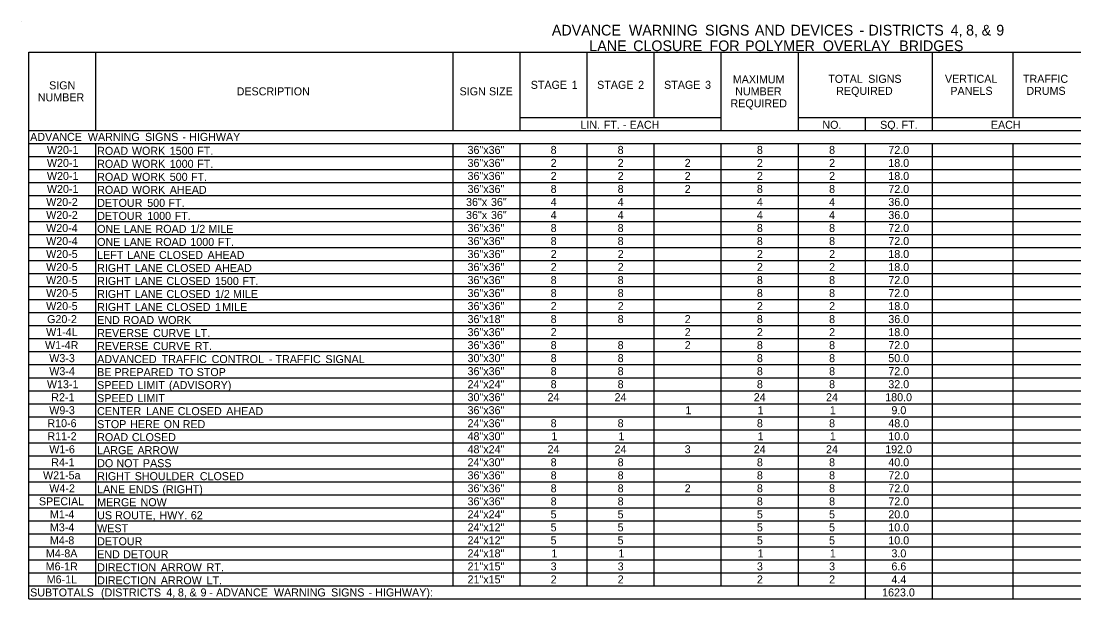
# Model space of a CAD drawing. Extents: x 544420 to 1930787, y -1947044 to 596640.
# Drawn here: x 544420 to 545209, y -1946626 to -1946193 of the extents above; entities that cross this region are included whole.
import ezdxf

# ---------------------------------------------------------------- set-up
doc = ezdxf.new("R2010")
doc.units = 0
doc.layers.add('Default', color=7, linetype='Continuous')

msp = doc.modelspace()

# ---------------------------------------------------------------- linework, layer by layer
at = {"layer": 'Default'}
for p, q in [((544420.05, -1946193.36), (544420.05, -1946193.36)), ((544425.9, -1946216.76), (545626.13, -1946216.76)), ((544425.9, -1946626.26), (544425.9, -1946216.76)), ((544425.9, -1946626.26), (544425.9, -1946216.76)), ((544476.12, -1946275.26), (544476.12, -1946216.76)), ((544743.75, -1946275.26), (544743.75, -1946216.76)), ((544793.97, -1946275.26), (544793.97, -1946216.76)), ((544844.18, -1946265.51), (544844.18, -1946216.76)), ((544894.39, -1946265.51), (544894.39, -1946216.76)), ((544944.6, -1946275.26), (544944.6, -1946216.76)), ((545002.62, -1946275.26), (545002.62, -1946216.76)), ((545103.04, -1946275.26), (545103.04, -1946216.76)), ((545163.49, -1946265.51), (545163.49, -1946216.76)), ((544793.97, -1946265.51), (544944.6, -1946265.51)), ((544944.6, -1946275.26), (544944.6, -1946265.51)), ((545002.62, -1946265.51), (545626.13, -1946265.51)), ((545052.83, -1946275.26), (545052.83, -1946265.51)), ((544425.9, -1946275.26), (545626.13, -1946275.26)), ((544944.6, -1946275.26), (545626.13, -1946275.26)), ((544425.9, -1946285.01), (545626.13, -1946285.01)), ((544476.12, -1946558.01), (544476.12, -1946285.01)), ((544476.12, -1946616.51), (544476.12, -1946285.01)), ((544743.75, -1946558.01), (544743.75, -1946285.01)), ((544743.75, -1946616.51), (544743.75, -1946285.01)), ((544793.97, -1946558.01), (544793.97, -1946285.01)), ((544793.97, -1946616.51), (544793.97, -1946285.01)), ((544844.18, -1946558.01), (544844.18, -1946285.01)), ((544844.18, -1946616.51), (544844.18, -1946285.01)), ((544894.39, -1946558.01), (544894.39, -1946285.01)), ((544894.39, -1946616.51), (544894.39, -1946285.01)), ((544944.6, -1946558.01), (544944.6, -1946285.01)), ((544944.6, -1946616.51), (544944.6, -1946285.01)), ((545002.62, -1946616.51), (545002.62, -1946285.01)), ((545052.83, -1946616.51), (545052.83, -1946285.01)), ((545052.83, -1946626.26), (545052.83, -1946285.01)), ((545103.04, -1946548.26), (545103.04, -1946285.01)), ((545103.04, -1946626.26), (545103.04, -1946285.01)), ((545163.49, -1946558.01), (545163.49, -1946285.01)), ((545163.49, -1946626.26), (545163.49, -1946285.01)), ((544425.9, -1946294.76), (545626.13, -1946294.76)), ((544425.9, -1946304.51), (545626.13, -1946304.51)), ((544425.9, -1946314.26), (545626.13, -1946314.26)), ((544425.9, -1946324.01), (545626.13, -1946324.01)), ((544425.9, -1946333.76), (545626.13, -1946333.76)), ((544425.9, -1946343.51), (545626.13, -1946343.51)), ((544425.9, -1946353.26), (545626.13, -1946353.26)), ((544425.9, -1946363.01), (545626.13, -1946363.01)), ((544425.9, -1946372.76), (545626.13, -1946372.76)), ((544425.9, -1946382.51), (545626.13, -1946382.51)), ((544425.9, -1946392.26), (545626.13, -1946392.26)), ((544425.9, -1946402.01), (545626.13, -1946402.01)), ((544425.9, -1946411.76), (545626.13, -1946411.76)), ((544425.9, -1946421.51), (545626.13, -1946421.51)), ((544425.9, -1946431.26), (545626.13, -1946431.26)), ((544425.9, -1946441.01), (545626.13, -1946441.01)), ((544425.9, -1946450.76), (545626.13, -1946450.76)), ((544425.9, -1946460.51), (545626.13, -1946460.51)), ((544425.9, -1946470.26), (545626.13, -1946470.26)), ((544425.9, -1946480.01), (545626.13, -1946480.01)), ((544425.9, -1946489.76), (545626.13, -1946489.76)), ((544425.9, -1946499.51), (545626.13, -1946499.51)), ((544425.9, -1946509.26), (545626.13, -1946509.26)), ((544425.9, -1946519.01), (545626.13, -1946519.01)), ((544425.9, -1946528.76), (545626.13, -1946528.76)), ((544425.9, -1946538.51), (545626.13, -1946538.51)), ((544425.9, -1946548.26), (545626.13, -1946548.26)), ((544425.9, -1946558.01), (545626.13, -1946558.01)), ((544425.9, -1946567.76), (545626.13, -1946567.76)), ((544425.9, -1946577.51), (545626.13, -1946577.51)), ((544425.9, -1946587.26), (545626.13, -1946587.26)), ((544425.9, -1946597.01), (545626.13, -1946597.01)), ((544425.9, -1946606.76), (545626.13, -1946606.76)), ((544425.9, -1946616.51), (545626.13, -1946616.51)), ((544944.6, -1946616.51), (545103.04, -1946616.51)), ((545103.04, -1946616.51), (545626.13, -1946616.51)), ((545103.04, -1946626.26), (545103.04, -1946616.51)), ((545163.49, -1946626.26), (545163.49, -1946616.51)), ((544425.9, -1946626.26), (545626.13, -1946626.26))]:
    msp.add_line(p, q, dxfattribs=at)

# ---------------------------------------------------------------- texts
for s, height, p in [('ADVANCE', 8, (544817.83, -1946204.18)), (' WARNING', 8, (544872.56, -1946204.18)), (' SIGNS', 8, (544929.62, -1946204.18)), (' AND', 8, (544966.96, -1946204.18)), (' DEVICES', 8, (544993.73, -1946204.18)), (' DISTRICTS', 8, (545052.11, -1946204.18)), (' 4,', 8, (545113.67, -1946204.18)), (' 8,', 8, (545125.28, -1946204.18)), (' &', 8, (545136.9, -1946204.18)), (' 9', 8, (545147.89, -1946204.18)), (' -', 8, (545045.37, -1946204.18)), ('LANE', 8, (544845.9, -1946215.88)), (' CLOSURE', 8, (544875.78, -1946215.88)), (' FOR', 8, (544932.99, -1946215.88)), (' POLYMER', 8, (544959.64, -1946215.88)), (' OVERLAY', 8, (545017.96, -1946215.88)), (' BRIDGES', 8, (545075.13, -1946215.88)), ('MAXIMUM', 6, (544953.42, -1946240.01)), ('TOTAL', 6, (545024.98, -1946239.63)), (' SIGNS', 6, (545052.67, -1946239.63)), ('VERTICAL', 6, (545112.43, -1946239.63)), ('TRAFFIC', 6, (545170.88, -1946239.63)), ('SIGN', 6, (544441.1, -1946244.51)), ('DESCRIPTION', 6, (544581.62, -1946249.01)), ('SIGN', 6, (544748.67, -1946249.01)), (' SIZE', 6, (544768.5, -1946249.01)), ('STAGE', 6, (544802.02, -1946244.13)), (' 1', 6, (544830.49, -1946244.13)), ('STAGE', 6, (544851.77, -1946244.13)), (' 2', 6, (544880.24, -1946244.13)), ('STAGE', 6, (544901.95, -1946244.13)), (' 3', 6, (544930.42, -1946244.13)), ('NUMBER', 6, (544955.23, -1946249.01)), ('REQUIRED', 6, (545030.91, -1946248.63)), ('PANELS', 6, (545116.47, -1946248.63)), ('DRUMS', 6, (545173.43, -1946248.63)), ('NUMBER', 6, (544432.63, -1946253.51)), ('REQUIRED', 6, (544951.69, -1946258.01)), ('LIN.', 6, (544839.25, -1946274.06)), (' FT.', 6, (544854.5, -1946274.06)), (' -', 6, (544868.83, -1946274.06)), (' EACH', 6, (544873.88, -1946274.06)), ('NO.', 6, (545020.56, -1946274.06)), ('SQ.', 6, (545063.84, -1946274.06)), (' FT.', 6, (545077.71, -1946274.06)), ('EACH', 6, (545146.82, -1946274.06)), ('ADVANCE', 6, (544426.88, -1946283.13)), (' WARNING', 6, (544467.92, -1946283.13)), (' SIGNS', 6, (544510.72, -1946283.13)), (' -', 6, (544538.73, -1946283.13)), (' HIGHWAY', 6, (544543.79, -1946283.13)), ('W20-1', 6, (544439.44, -1946292.88)), ('ROAD', 6, (544477.09, -1946293.56)), (' WORK', 6, (544500.87, -1946293.56)), (' 1500', 6, (544529.26, -1946293.56)), (' FT.', 6, (544549.82, -1946293.56)), ('36"x36"', 6, (544754.66, -1946292.88)), ('8', 6, (544816.93, -1946292.88)), ('8', 6, (544867.14, -1946292.88)), ('8', 6, (544971.47, -1946292.88)), ('8', 6, (545025.58, -1946292.88)), ('72.0', 6, (545069.98, -1946292.88)), ('W20-1', 6, (544439.44, -1946302.63)), ('ROAD', 6, (544477.09, -1946303.31)), (' WORK', 6, (544500.87, -1946303.31)), (' 1000', 6, (544529.26, -1946303.31)), (' FT.', 6, (544549.82, -1946303.31)), ('36"x36"', 6, (544754.66, -1946302.63)), ('2', 6, (544816.96, -1946302.63)), ('2', 6, (544867.18, -1946302.63)), ('2', 6, (544917.39, -1946302.63)), ('2', 6, (544971.5, -1946302.63)), ('2', 6, (545025.61, -1946302.63)), ('18.0', 6, (545069.98, -1946302.63)), ('W20-1', 6, (544439.44, -1946312.38)), ('36"x36"', 6, (544754.66, -1946312.38)), ('2', 6, (544816.96, -1946312.38)), ('2', 6, (544867.18, -1946312.38)), ('2', 6, (544917.39, -1946312.38)), ('2', 6, (544971.5, -1946312.38)), ('2', 6, (545025.61, -1946312.38)), ('18.0', 6, (545069.98, -1946312.38)), ('ROAD', 6, (544477.09, -1946313.06)), (' WORK', 6, (544500.87, -1946313.06)), (' 500', 6, (544529.26, -1946313.06)), (' FT.', 6, (544545.16, -1946313.06)), ('W20-1', 6, (544439.44, -1946322.13)), ('ROAD', 6, (544477.09, -1946322.81)), (' WORK', 6, (544500.87, -1946322.81)), (' AHEAD', 6, (544529.26, -1946322.81)), ('36"x36"', 6, (544754.66, -1946322.13)), ('8', 6, (544816.93, -1946322.13)), ('8', 6, (544867.14, -1946322.13)), ('2', 6, (544917.39, -1946322.13)), ('8', 6, (544971.47, -1946322.13)), ('8', 6, (545025.58, -1946322.13)), ('72.0', 6, (545069.98, -1946322.13)), ('W20-2', 6, (544438.89, -1946331.88)), ('DETOUR', 6, (544477.09, -1946332.56)), (' 500', 6, (544512.38, -1946332.56)), (' FT.', 6, (544528.28, -1946332.56)), ('36"x', 6, (544753.53, -1946331.88)), (' 36"', 6, (544769.96, -1946331.88)), ('4', 6, (544816.95, -1946331.88)), ('4', 6, (544867.16, -1946331.88)), ('4', 6, (544971.48, -1946331.88)), ('4', 6, (545025.6, -1946331.88)), ('36.0', 6, (545069.98, -1946331.88)), ('W20-2', 6, (544438.89, -1946341.63)), ('DETOUR', 6, (544477.09, -1946342.31)), (' 1000', 6, (544512.38, -1946342.31)), (' FT.', 6, (544532.94, -1946342.31)), ('36"x', 6, (544753.53, -1946341.63)), (' 36"', 6, (544769.96, -1946341.63)), ('4', 6, (544816.95, -1946341.63)), ('4', 6, (544867.16, -1946341.63)), ('4', 6, (544971.48, -1946341.63)), ('4', 6, (545025.6, -1946341.63)), ('36.0', 6, (545069.98, -1946341.63)), ('W20-4', 6, (544438.87, -1946351.38)), ('ONE', 6, (544477.09, -1946352.06)), (' LANE', 6, (544494.81, -1946352.06)), (' ROAD', 6, (544518.59, -1946352.06)), (' 1/2', 6, (544544.7, -1946352.06)), (' MILE', 6, (544558.23, -1946352.06)), ('36"x36"', 6, (544754.66, -1946351.38)), ('8', 6, (544816.93, -1946351.38)), ('8', 6, (544867.14, -1946351.38)), ('8', 6, (544971.47, -1946351.38)), ('8', 6, (545025.58, -1946351.38)), ('72.0', 6, (545069.98, -1946351.38)), ('W20-4', 6, (544438.87, -1946361.13)), ('ONE', 6, (544477.09, -1946361.81)), (' LANE', 6, (544494.81, -1946361.81)), (' ROAD', 6, (544518.59, -1946361.81)), (' 1000', 6, (544544.7, -1946361.81)), (' FT.', 6, (544565.26, -1946361.81)), ('36"x36"', 6, (544754.66, -1946361.13)), ('8', 6, (544816.93, -1946361.13)), ('8', 6, (544867.14, -1946361.13)), ('8', 6, (544971.47, -1946361.13)), ('8', 6, (545025.58, -1946361.13)), ('72.0', 6, (545069.98, -1946361.13)), ('W20-5', 6, (544438.84, -1946370.88)), ('LEFT', 6, (544477.09, -1946371.56)), (' LANE', 6, (544497.42, -1946371.56)), (' CLOSED', 6, (544521.2, -1946371.56)), (' AHEAD', 6, (544557.56, -1946371.56)), ('36"x36"', 6, (544754.66, -1946370.88)), ('2', 6, (544816.96, -1946370.88)), ('2', 6, (544867.18, -1946370.88)), ('2', 6, (544971.5, -1946370.88)), ('2', 6, (545025.61, -1946370.88)), ('18.0', 6, (545069.98, -1946370.88)), ('W20-5', 6, (544438.84, -1946380.63)), ('RIGHT', 6, (544477.09, -1946381.31)), (' LANE', 6, (544503, -1946381.31)), (' CLOSED', 6, (544526.78, -1946381.31)), (' AHEAD', 6, (544563.14, -1946381.31)), ('36"x36"', 6, (544754.66, -1946380.63)), ('2', 6, (544816.96, -1946380.63)), ('2', 6, (544867.18, -1946380.63)), ('2', 6, (544971.5, -1946380.63)), ('2', 6, (545025.61, -1946380.63)), ('18.0', 6, (545069.98, -1946380.63)), ('W20-5', 6, (544438.84, -1946390.38)), ('RIGHT', 6, (544477.09, -1946391.06)), (' LANE', 6, (544503, -1946391.06)), (' CLOSED', 6, (544526.78, -1946391.06)), (' 1500', 6, (544563.14, -1946391.06)), (' FT.', 6, (544583.71, -1946391.06)), ('36"x36"', 6, (544754.66, -1946390.38)), ('8', 6, (544816.93, -1946390.38)), ('8', 6, (544867.14, -1946390.38)), ('8', 6, (544971.47, -1946390.38)), ('8', 6, (545025.58, -1946390.38)), ('72.0', 6, (545069.98, -1946390.38)), ('W20-5', 6, (544438.84, -1946400.13)), ('RIGHT', 6, (544477.09, -1946400.81)), (' LANE', 6, (544503, -1946400.81)), (' CLOSED', 6, (544526.78, -1946400.81)), (' 1/2', 6, (544563.14, -1946400.81)), (' MILE', 6, (544576.67, -1946400.81)), ('36"x36"', 6, (544754.66, -1946400.13)), ('8', 6, (544816.93, -1946400.13)), ('8', 6, (544867.14, -1946400.13)), ('8', 6, (544971.47, -1946400.13)), ('8', 6, (545025.58, -1946400.13)), ('72.0', 6, (545069.98, -1946400.13)), ('W20-5', 6, (544438.84, -1946409.88)), ('RIGHT', 6, (544477.09, -1946410.56)), (' LANE', 6, (544503, -1946410.56)), (' CLOSED', 6, (544526.78, -1946410.56)), (' 1', 6, (544563.14, -1946410.56)), (' MILE', 6, (544568.59, -1946410.56)), ('36"x36"', 6, (544754.66, -1946409.88)), ('2', 6, (544816.96, -1946409.88)), ('2', 6, (544867.18, -1946409.88)), ('2', 6, (544971.5, -1946409.88)), ('2', 6, (545025.61, -1946409.88)), ('18.0', 6, (545069.98, -1946409.88)), ('G20-2', 6, (544439.59, -1946419.63)), ('END', 6, (544477.09, -1946420.31)), (' ROAD', 6, (544494.35, -1946420.31)), (' WORK', 6, (544520.45, -1946420.31)), ('36"x18"', 6, (544754.66, -1946419.63)), ('8', 6, (544816.93, -1946419.63)), ('8', 6, (544867.14, -1946419.63)), ('2', 6, (544917.39, -1946419.63)), ('8', 6, (544971.47, -1946419.63)), ('8', 6, (545025.58, -1946419.63)), ('36.0', 6, (545069.98, -1946419.63)), ('W1-4L', 6, (544438.82, -1946429.38)), ('REVERSE', 6, (544477.09, -1946430.06)), (' CURVE', 6, (544516.72, -1946430.06)), (' LT.', 6, (544547.95, -1946430.06)), ('36"x36"', 6, (544754.66, -1946429.38)), ('2', 6, (544816.96, -1946429.38)), ('2', 6, (544917.39, -1946429.38)), ('2', 6, (544971.5, -1946429.38)), ('2', 6, (545025.61, -1946429.38)), ('18.0', 6, (545069.98, -1946429.38)), ('W1-4R', 6, (544438.03, -1946439.13)), ('36"x36"', 6, (544754.66, -1946439.13)), ('8', 6, (544816.93, -1946439.13)), ('8', 6, (544867.14, -1946439.13)), ('2', 6, (544917.39, -1946439.13)), ('8', 6, (544971.47, -1946439.13)), ('8', 6, (545025.58, -1946439.13)), ('72.0', 6, (545069.98, -1946439.13)), ('REVERSE', 6, (544477.09, -1946439.81)), (' CURVE', 6, (544516.72, -1946439.81)), (' RT.', 6, (544547.95, -1946439.81)), ('W3-3', 6, (544441.19, -1946448.88)), ('ADVANCED', 6, (544477.09, -1946449.56)), (' TRAFFIC', 6, (544523.23, -1946449.56)), (' CONTROL', 6, (544560.63, -1946449.56)), (' -', 6, (544603.64, -1946449.56)), (' TRAFFIC', 6, (544608.5, -1946449.56)), (' SIGNAL', 6, (544645.89, -1946449.56)), ('30"x30"', 6, (544754.66, -1946448.88)), ('8', 6, (544816.93, -1946448.88)), ('8', 6, (544867.14, -1946448.88)), ('8', 6, (544971.47, -1946448.88)), ('8', 6, (545025.58, -1946448.88)), ('50.0', 6, (545069.98, -1946448.88)), ('W3-4', 6, (544441.2, -1946458.63)), ('BE', 6, (544477.09, -1946459.31)), (' PREPARED', 6, (544487.83, -1946459.31)), (' TO', 6, (544535.84, -1946459.31)), (' STOP', 6, (544549.43, -1946459.31)), ('36"x36"', 6, (544754.66, -1946458.63)), ('8', 6, (544816.93, -1946458.63)), ('8', 6, (544867.14, -1946458.63)), ('8', 6, (544971.47, -1946458.63)), ('8', 6, (545025.58, -1946458.63)), ('72.0', 6, (545069.98, -1946458.63)), ('W13-1', 6, (544439.44, -1946468.38)), ('SPEED', 6, (544477.09, -1946469.06)), (' LIMIT', 6, (544505.07, -1946469.06)), (' (ADVISORY)', 6, (544528.65, -1946469.06)), ('24"x24"', 6, (544754.66, -1946468.38)), ('8', 6, (544816.93, -1946468.38)), ('8', 6, (544867.14, -1946468.38)), ('8', 6, (544971.47, -1946468.38)), ('8', 6, (545025.58, -1946468.38)), ('32.0', 6, (545069.98, -1946468.38)), ('R2-1', 6, (544442.7, -1946478.13)), ('30"x36"', 6, (544754.66, -1946478.13)), ('24', 6, (544814.62, -1946478.13)), ('24', 6, (544864.83, -1946478.13)), ('24', 6, (544969.15, -1946478.13)), ('24', 6, (545023.27, -1946478.13)), ('180.0', 6, (545067.65, -1946478.13)), ('SPEED', 6, (544477.09, -1946478.81)), (' LIMIT', 6, (544505.07, -1946478.81)), ('W9-3', 6, (544441.19, -1946487.88)), ('CENTER', 6, (544477.09, -1946488.56)), (' LANE', 6, (544511.45, -1946488.56)), (' CLOSED', 6, (544535.23, -1946488.56)), (' AHEAD', 6, (544571.59, -1946488.56)), ('36"x36"', 6, (544754.66, -1946487.88)), ('1', 6, (544917.94, -1946487.88)), ('1', 6, (544972.05, -1946487.88)), ('1', 6, (545026.16, -1946487.88)), ('9.0', 6, (545072.31, -1946487.88)), ('R10-6', 6, (544439.79, -1946497.63)), ('STOP', 6, (544477.09, -1946498.31)), (' HERE', 6, (544499.55, -1946498.31)), (' ON', 6, (544524.73, -1946498.31)), (' RED', 6, (544538.95, -1946498.31)), ('24"x36"', 6, (544754.66, -1946497.63)), ('8', 6, (544816.93, -1946497.63)), ('8', 6, (544867.14, -1946497.63)), ('8', 6, (544971.47, -1946497.63)), ('8', 6, (545025.58, -1946497.63)), ('48.0', 6, (545069.98, -1946497.63)), ('R11-2', 6, (544439.82, -1946507.38)), ('ROAD', 6, (544477.09, -1946508.06)), (' CLOSED', 6, (544500.87, -1946508.06)), ('48"x30"', 6, (544754.66, -1946507.38)), ('1', 6, (544817.51, -1946507.38)), ('1', 6, (544867.73, -1946507.38)), ('1', 6, (544972.05, -1946507.38)), ('1', 6, (545026.16, -1946507.38)), ('10.0', 6, (545069.98, -1946507.38)), ('W1-6', 6, (544441.19, -1946517.13)), ('LARGE', 6, (544477.09, -1946517.81)), (' ARROW', 6, (544505.07, -1946517.81)), ('48"x24"', 6, (544754.66, -1946517.13)), ('24', 6, (544814.62, -1946517.13)), ('24', 6, (544864.83, -1946517.13)), ('3', 6, (544917.36, -1946517.13)), ('24', 6, (544969.15, -1946517.13)), ('24', 6, (545023.27, -1946517.13)), ('192.0', 6, (545067.65, -1946517.13)), ('R4-1', 6, (544442.7, -1946526.88)), ('DO', 6, (544477.09, -1946527.56)), (' NOT', 6, (544489.29, -1946527.56)), (' PASS', 6, (544509.15, -1946527.56)), ('24"x30"', 6, (544754.66, -1946526.88)), ('8', 6, (544816.93, -1946526.88)), ('8', 6, (544867.14, -1946526.88)), ('8', 6, (544971.47, -1946526.88)), ('8', 6, (545025.58, -1946526.88)), ('40.0', 6, (545069.98, -1946526.88)), ('W21-5a', 6, (544436.52, -1946536.63)), ('RIGHT', 6, (544477.09, -1946537.31)), (' SHOULDER', 6, (544503, -1946537.31)), (' CLOSED', 6, (544551.8, -1946537.31)), ('36"x36"', 6, (544754.66, -1946536.63)), ('8', 6, (544816.93, -1946536.63)), ('8', 6, (544867.14, -1946536.63)), ('8', 6, (544971.47, -1946536.63)), ('8', 6, (545025.58, -1946536.63)), ('72.0', 6, (545069.98, -1946536.63)), ('W4-2', 6, (544441.22, -1946546.38)), ('LANE', 6, (544477.09, -1946547.06)), (' ENDS', 6, (544498.54, -1946547.06)), (' (RIGHT)', 6, (544523.73, -1946547.06)), ('36"x36"', 6, (544754.66, -1946546.38)), ('8', 6, (544816.93, -1946546.38)), ('8', 6, (544867.14, -1946546.38)), ('2', 6, (544917.39, -1946546.38)), ('8', 6, (544971.47, -1946546.38)), ('8', 6, (545025.58, -1946546.38)), ('72.0', 6, (545069.98, -1946546.38)), ('SPECIAL', 6, (544433.45, -1946556.13)), ('MERGE', 6, (544477.09, -1946556.81)), (' NOW', 6, (544507.39, -1946556.81)), ('36"x36"', 6, (544754.66, -1946556.13)), ('8', 6, (544816.93, -1946556.13)), ('8', 6, (544867.14, -1946556.13)), ('8', 6, (544971.47, -1946556.13)), ('8', 6, (545025.58, -1946556.13)), ('72.0', 6, (545069.98, -1946556.13)), ('M1-4', 6, (544441.67, -1946565.88)), ('US', 6, (544477.09, -1946566.56)), (' ROUTE,', 6, (544488.3, -1946566.56)), (' HWY.', 6, (544521.56, -1946566.56)), (' 62', 6, (544545.04, -1946566.56)), ('24"x24"', 6, (544754.66, -1946565.88)), ('5', 6, (544816.91, -1946565.88)), ('5', 6, (544867.12, -1946565.88)), ('5', 6, (544971.45, -1946565.88)), ('5', 6, (545025.56, -1946565.88)), ('20.0', 6, (545069.98, -1946565.88)), ('M3-4', 6, (544441.67, -1946575.63)), ('WEST', 6, (544477.09, -1946576.31)), ('24"x12"', 6, (544754.66, -1946575.63)), ('5', 6, (544816.91, -1946575.63)), ('5', 6, (544867.12, -1946575.63)), ('5', 6, (544971.45, -1946575.63)), ('5', 6, (545025.56, -1946575.63)), ('10.0', 6, (545069.98, -1946575.63)), ('M4-8', 6, (544441.65, -1946585.38)), ('DETOUR', 6, (544477.09, -1946586.06)), ('24"x12"', 6, (544754.66, -1946585.38)), ('5', 6, (544816.91, -1946585.38)), ('5', 6, (544867.12, -1946585.38)), ('5', 6, (544971.45, -1946585.38)), ('5', 6, (545025.56, -1946585.38)), ('10.0', 6, (545069.98, -1946585.38)), ('M4-8A', 6, (544438.66, -1946595.13)), ('END', 6, (544477.09, -1946595.81)), (' DETOUR', 6, (544494.35, -1946595.81)), ('24"x18"', 6, (544754.66, -1946595.13)), ('1', 6, (544817.51, -1946595.13)), ('1', 6, (544867.73, -1946595.13)), ('1', 6, (544972.05, -1946595.13)), ('1', 6, (545026.16, -1946595.13)), ('3.0', 6, (545072.31, -1946595.13)), ('M6-1R', 6, (544438.49, -1946604.88)), ('21"x15"', 6, (544754.66, -1946604.88)), ('3', 6, (544816.93, -1946604.88)), ('3', 6, (544867.15, -1946604.88)), ('3', 6, (544971.47, -1946604.88)), ('3', 6, (545025.58, -1946604.88)), ('6.6', 6, (545072.3, -1946604.88)), ('DIRECTION', 6, (544477.09, -1946605.56)), (' ARROW', 6, (544522.52, -1946605.56)), (' RT.', 6, (544556.88, -1946605.56)), ('M6-1L', 6, (544439.28, -1946614.63)), ('DIRECTION', 6, (544477.09, -1946615.31)), (' ARROW', 6, (544522.52, -1946615.31)), (' LT.', 6, (544556.88, -1946615.31)), ('21"x15"', 6, (544754.66, -1946614.63)), ('2', 6, (544816.96, -1946614.63)), ('2', 6, (544867.18, -1946614.63)), ('2', 6, (544971.5, -1946614.63)), ('2', 6, (545025.61, -1946614.63)), ('4.4', 6, (545072.31, -1946614.63)), ('SUBTOTALS', 6, (544426.88, -1946624.38)), (' (DISTRICTS', 6, (544477.71, -1946624.38)), (' 4,', 6, (544526.66, -1946624.38)), (' 8,', 6, (544535.37, -1946624.38)), (' &', 6, (544544.08, -1946624.38)), (' 9', 6, (544552.33, -1946624.38)), (' -', 6, (544558.93, -1946624.38)), (' ADVANCE', 6, (544563.99, -1946624.38)), (' WARNING', 6, (544607.36, -1946624.38)), (' SIGNS', 6, (544650.16, -1946624.38)), (' -', 6, (544678.17, -1946624.38)), (' HIGHWAY):', 6, (544683.22, -1946624.38)), ('1623.0', 6, (545065.33, -1946624.38))]:
    msp.add_text(s, height=height, dxfattribs=at).set_placement(p)

doc.saveas('drawing.dxf')
